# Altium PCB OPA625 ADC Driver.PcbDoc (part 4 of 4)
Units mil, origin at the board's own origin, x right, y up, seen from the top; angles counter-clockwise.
Board outline 4590 x 3930 mil, 4 copper layers (Layer 1 - Top Layer, Layer 2 - GND, Layer 3 - PWR, Layer 4 - Bottom Layer), stack 59.034 mil thick; 428 components, 236 nets, 1203 pads, 546 vias.
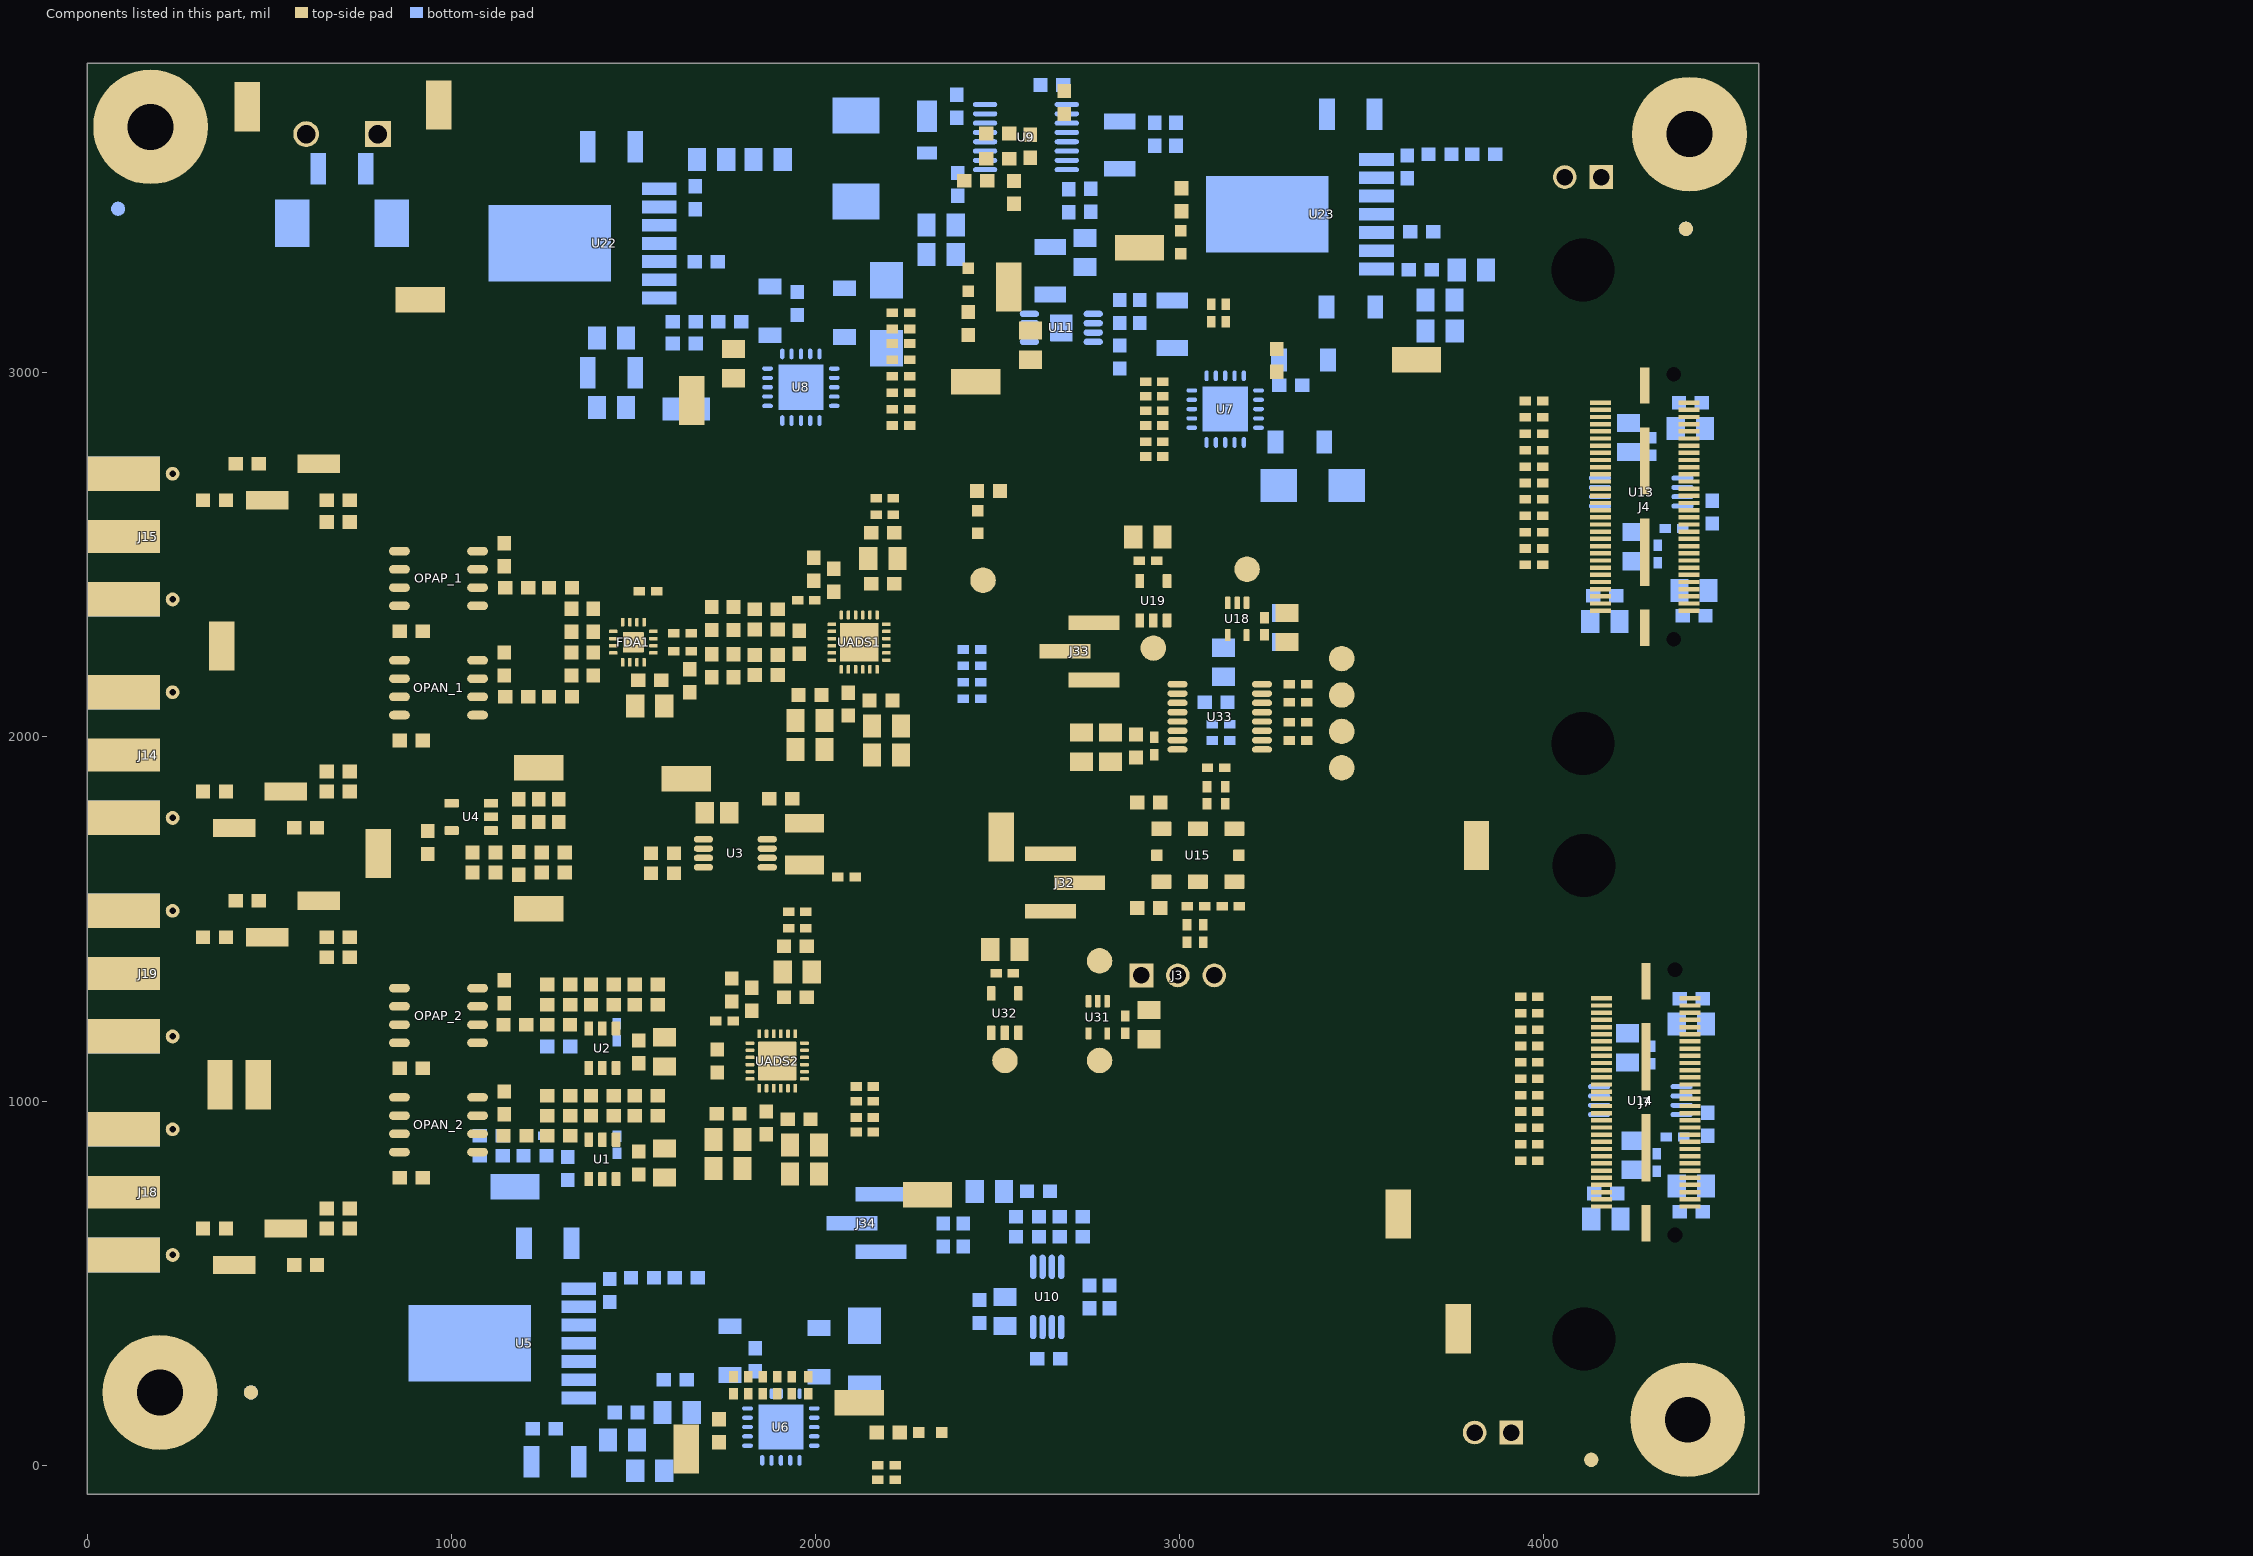
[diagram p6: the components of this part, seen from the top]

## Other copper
Layer 1 - Top Layer:
  region net GND: 4271.85,2222.58 4291.85,2222.58 4291.85,2357.58 4322.34,2388.07 4322.34,2882.08 4291.85,2912.57 4291.85,3042.58 4271.85,3042.58 4261.85,3032.58 4231.85,3002.58 4231.85,2262.58 4261.85,2232.58
  region net GND: 2555.21,3060.7 2630.21,3060.7 2645.21,3075.7 2645.21,3150.7 2655.21,3160.7 2695.21,3160.7 2706.28,3149.63 2706.28,3086.77 2730,3063.05 2745,3048.05 2745,2958.05 2732.65,2945.7 2580.21,2945.7 2555.21,2970.7
  region net GND: 4274.99,1406.32 4294.99,1406.32 4294.99,1271.32 4324.99,1241.32 4324.99,746.32 4294.99,716.32 4294.99,586.32 4274.99,586.32 4264.99,596.32 4235,626.32 4235,1366.32 4264.99,1396.32
  region net GND: 3217.81,2310.8 3332.81,2310.8 3332.81,2430.3 3270,2430.3 3217.81,2378.1
  region net AGND: 2195,2400 2245,2400 2275,2430 2275,2525 2195,2525
  region net 3.3V: 2280,1918 2210,1918 2210,1982 2280,1982
  region net AGND: 2279.45,1998 2279.45,2095 2254.45,2120 2199.45,2120 2190,2120 2190,2080 2210,2060 2210,1998
  region net NetC88_2: 2065,2198 2065,2105 2070,2100 2080,2100 2110,2100 2110,2150 2096,2164 2096,2198
  region net AGND: 1895,2013 1895,2110 1920,2135 1975,2135 1975,2013
  region net NetFDA1_13: 1535,2303 1535,2415 1485,2415 1465,2395 1465,2303
  region net AGND: 1555,2175 1555,2055 1565,2045 1640,2045 1675,2080 1675,2145 1630,2145 1620,2155 1620,2175
  region net 5V: 1535,2217 1535,2055 1525,2045 1455,2045 1455,2160 1465,2170 1465,2217
  region net 3.3V: 2695.01,1960.01 2695.01,1890.01 2705.01,1880.01 2835.01,1880.01 2845.01,1890.01 2845.01,1960.01
  region net GND: 2695.01,1985.01 2695.01,2060.01 2705.01,2070.01 2752.01,2070.01 2762.01,2060.01 2762.01,1985.01
  region net VDD: 3022,1982 2786,1982 2778,1990 2778,2058 2848,2128 3022,2128 3022,2058 2958,2058 2945,2045 2945,2015 2960,2000 3022,2000
  region net AGND: 1955,1265 2005,1265 2035,1295 2035,1390 1955,1390
  region net 3.3V: 2045,765 1985,765 1985,832 2042.45,832 2054.45,820 2054.45,774.45
  region net NetC119_1: 1840,1048 1840,955 1845,950 1855,950 1885,950 1885,1000 1871,1014 1871,1048
  region net 5V: 1670,780 1750,780 1750,847 1670,847
  region net AGND: 1670,863 1670,960 1695,985 1750,985 1750,863
  region net AGND: 1640,840 1495,840 1495,880 1515,900 1630,900 1640,890
  region net 5V: 1440,805 1455,820 1640,820 1640,765 1440,765
  region net AGND: 2048,848 2055,855 2055,925 2010,970 1974.45,970 1965,970 1965,930 1985,910 1985,848
  region net +24VDC: 845,3160 985,3160 985,3286.12 975,3296.12 855,3296.12 845,3286.12
  region net NetC9_1: 1620,2993.54 1620,2853.54 1710,2853.54 1720,2863.54 1720,2983.54 1710,2993.54
  region net +18V: 2305.75,3130 2305.75,2935 2439.46,2935 2511.71,2935 2511.71,3026.49 2445.75,3026.49 2445.75,3130
  region net AGND: 1640,1145 1495,1145 1495,1185 1515,1205 1630,1205 1640,1195
  region net 5V: 1440,1125 1640,1125 1640,1070 1440,1070
  region net AGND: 1270,1660.26 1230,1660.26 1225,1665.26 1225,1705.26 1210,1720.26 1165,1720.26 1150,1735.26 1150,1756.26 1139,1767.26 1089,1767.26 1089,1792.26 1253,1792.26 1260,1785.26 1260,1735.26 1270,1725.26
  region net AGND: 1563.79,1704.41 1569.79,1698.41 1569.79,1605.41 1515.79,1605.41 1504.79,1616.41 1504.79,1645.41 1504.79,1695 1514.2,1704.41
  region net VREF: 1840.79,1677.41 2072.79,1677.41 2079.79,1670.41 2079.79,1605.41 2069.79,1595.41 1875.79,1595.41 1840.79,1630.41
  region net NetC5_2: 2024.79,1735.41 2024.79,1800.41 1974.79,1850.41 1914.79,1850.41 1914.79,1735.41
  region net AGND: 1894.79,1683.41 1894.79,1850.41 1756.79,1850.41 1736.79,1830.41 1736.79,1743.41 1796.79,1683.41
  region net 3.3V: 2907.81,2403.82 2907.81,2602.19 2895,2615 2845,2615 2832.81,2602.81 2832.81,2448.82 2877.81,2403.82
  region net GND: 2919.81,2470.82 2954.81,2470.82 2982.81,2498.82 2982.81,2607.19 2975,2615 2930,2615 2919.81,2604.81
  region net 3.3V: 3174.81,2296.82 3332.81,2296.82 3332.81,2223.82 3317.81,2208.82 3204.81,2208.82 3174.81,2238.82
  region net GND: 2526.83,1338.55 2561.83,1338.55 2589.83,1366.55 2589.83,1466.55 2579.83,1476.55 2540.83,1476.55 2526.83,1462.55
  region net 3.3V: 2513,1271.55 2513,1462 2498.45,1476.55 2451.55,1476.55 2440,1465 2440,1301.38 2469.83,1271.55
  region net GND: 2835.21,1215 2960.21,1215 2970.21,1225 2970.21,1275 2960.21,1285 2870.21,1285 2835.21,1250
  region net 3.3V: 2792.21,1203 2792.21,1168 2820.21,1140 2960.21,1140 2970.21,1150 2970.21,1196 2963.21,1203
  region net -18.5V: 2569.51,3305 2489.51,3305 2474.51,3290 2474.51,3175 2489.51,3160 2569.51,3160
  region net VDDO: 3254,2008 3152,2008 3135,2025 3135,2105 3159,2129 3254,2129 3254,2110 3188,2110 3175,2097 3175,2037 3186,2026 3254,2026
  region net 3.3V: 2048.93,211.07 2048.93,97.07 2078.93,67.07 2188.93,67.07 2188.93,211.07
  region net 5V: 1975,1930 1905,1930 1895,1940 1895,1987 1905,1997 1975,1997
  region net 5V: 1723,1693 1714,1684 1671,1684 1570,1785 1570,1915 1585,1930 1705,1930 1723,1912
  text ".Layer_Name" at 577,-1158.49 h60
Layer 2 - GND:
  text ".Layer_Name" at 577,-1158.49 h60
Layer 3 - PWR:
  region net GND: 760,3545 930,3545 965,3580 965,3660 930,3695 760,3695
  pour cut-out: 4205,1575.49 4205.2,1575.49 cw(c4205.2,1550.25) 4230.44,1550.25 4230.44,1549.95 cw(c4205,1549.95) 4205,1524.51 cw(c4205,1550) 4179.51,1550 cw(c4205,1550)
  pour cut-out: 5770,1830.49 5770.2,1830.49 cw(c5770.2,1805.25) 5795.44,1805.25 5795.44,1804.95 cw(c5770,1804.95) 5770,1779.51 cw(c5770,1805) 5744.51,1805 cw(c5770,1805)
  pour cut-out: 4865,1595.49 4865.2,1595.49 cw(c4865.2,1570.25) 4890.44,1570.25 4890.44,1569.95 cw(c4865,1569.95) 4865,1544.51 cw(c4865,1570) 4839.51,1570 cw(c4865,1570)
  pour cut-out: 4797.95,1575.49 4798.15,1575.49 cw(c4798.15,1550.25) 4823.39,1550.25 4823.39,1549.95 cw(c4797.95,1549.95) 4797.95,1524.51 cw(c4797.95,1550) 4772.46,1550 cw(c4797.95,1550)
  pour cut-out: 5795,2000.49 5795.2,2000.49 cw(c5795.2,1975.25) 5820.44,1975.25 5820.44,1974.95 cw(c5795,1974.95) 5795,1949.51 cw(c5795,1975) 5769.51,1975 cw(c5795,1975)
  pour cut-out: 5770,2264.98 5770.2,2264.98 cw(c5770.2,2239.73) 5795.44,2239.73 5795.44,2239.44 cw(c5770,2239.44) 5770,2214 cw(c5770,2239.49) 5744.51,2239.49 cw(c5770,2239.49)
  pour cut-out: 4187.5,2038.01 4187.7,2038.01 cw(c4187.7,2012.77) 4212.94,2012.77 4212.94,2012.47 cw(c4187.5,2012.47) 4187.5,1987.03 cw(c4187.5,2012.52) 4162.01,2012.52 cw(c4187.5,2012.52)
  pour cut-out: 5785,1965.49 5785.2,1965.49 cw(c5785.2,1940.25) 5810.44,1940.25 5810.44,1939.95 cw(c5785,1939.95) 5785,1914.51 cw(c5785,1940) 5759.51,1940 cw(c5785,1940)
  text ".Layer_Name" at 577,-1158.49 h60
Layer 4 - Bottom Layer:
  region net AGND: 1213.5,1171.5 1283.5,1171.5 1283.5,1121.5 1213.5,1121.5
  region net NetR252_1: 1405,1185 1465,1185 1470,1180 1470,1100 1465,1095 1435,1095 1405,1125
  region net AGND: 1270,805 1340,805 1340,755 1270,755
  region net GND: 3320,2315 3320,2420 3310,2430 3260,2430 3250,2420 3250,2315
  region net GND: 842.76,440 1062.76,660 1232.76,660 1232.76,379 1257.76,354 1376.76,354 1401.76,354 1412.76,365 1578.95,365 1650,425 1650,555 1694,555 1694,105 1625,105 1625,258.61 1578.61,305 1409.56,305 1396.56,318 1257.76,318 1240,300.24 1240,-45 1117.76,-45 842.76,230
  region net -18V: 2851.18,3175.88 3020.18,3175.88 3031.18,3186.88 3031.18,3241.88 2975.05,3298 2851.18,3298
  region net VDDO: 3175,1995 3155,1975 3120,1975 3120,2060 3110,2070 3110,2115 3080,2145 3080,2190 3150,2190 3175,2165
  region net 3.3V: 3080,2215.3 3310,2215.3 3320,2225.3 3320,2290.3 3100.3,2290.3 3080,2270
  region net +24VDC_IN: 685,3680 660,3705 515,3705 380,3570 380,3340 660,3340 685,3365
  region net GND: 740,3515 740,3680 765,3705 935,3705 960,3680 960,3585 860,3585 790,3515
  region net 18.5V: 1630,3218.75 1630,2865 1455,2865 1455,2925.69 1484.31,2955 1484.31,3014.31 1455,3043.61 1455,3139.37 1472.81,3157.19 1472.81,3217.65 1610,3218.61
  region net GND: 1826.02,3200 1944.87,3200 2143.55,3200 2143.54,3350 2000,3350 1944.87,3405.12 1944.87,3613.54 1880,3613.54 1880,3434 1786,3434 1720,3368 1462,3368 1450,3380 1450,3620 1400,3670 1135,3670 1020,3555 1020,3200 1020,3130 1285,2865 1425,2865 1425,3125 1450,3150 1450,3320 1462,3332 1715,3332 1715,3273.62 1730.62,3273.62 1792.12,3212.12 1792.12,3111.46 1826.02,3111.46
  region net GND: 2170,3615 2170,3520 2240,3450 2330,3450 2330,3335 2330,3292.5 2237.5,3292.5 2195,3335 2170,3335 2045,3335 2045,3615
  region net GND: 2643,3240 2600,3240 2600,3191.05 2643,3191.05 2643,3041.05 2600,2998.05 2555,2998.05 2555,2952.05 2850,2952.05 2866,2968.05 2957,2968.05 3030,3041.05 3030,3092.05 2939,3092.05 2888,3041.05 2795,3041.05 2795,3082.05 2785,3092.05 2719,3092.05 2706,3105.05 2706,3240
  region net GND: 3889.76,3490 3889.76,3640 3844.76,3640 3844.76,3530 3774.76,3460 3672.76,3460 3608.76,3460 3598.76,3450 3479.76,3450 3464.76,3465 3464.76,3525 3444.76,3545 3444.76,3820 3369.76,3820 3369.76,3596 3318.76,3545 3064.76,3545 3064.76,3325 3318.76,3325 3369.76,3274 3369.76,3085 3444.76,3085 3444.76,3325 3464.76,3345 3464.76,3399 3479.76,3414 3664.76,3414 3664.76,3360 3789.76,3360 3812.76,3337 3812.76,3250 3889.76,3250 3889.76,3414
  region net -0.2V: 2204.75,787.23 2204.75,677.23 2239.75,642.23 2457.25,642.23 2457.25,689.73 2467.25,699.73 2467.25,787.23
  region net NetC33_1: 2423,419.23 2599,419.23 2609,409.23 2609,358.23 2593,342.23 2457.25,342.23 2423,376.47
  region net 3.3V: 2485.27,435.23 2550.27,435.23 2560.27,445.23 2560.27,507.23 2550.27,517.23 2495.27,517.23 2485.27,507.23
  region net NetR250_1: 1405,860 1418,873 1518,873 1523,868 1523,838 1500,815 1405,815
  text ".Layer_Name" at 577,-1158.49 h60

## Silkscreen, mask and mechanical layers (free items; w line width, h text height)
Top Overlay:
  lines w10: 1615,945 1655,905 1655,635 ; 1640,2520 1640,2505 1760,2505 1760,2520 ; 1665,2325 1665,2505 ; 1635,500 2010,500 2010,635 1635,635 1635,500
  lines w20: 405,3480 455,3480 ; 430,3455 430,3505 ; 935.69,3482.89 985.69,3482.89
  text "-18.5V" at 2468.31,3323.54 h50
  text "-18V" at 2705,3275 h50
  text "+24VDC" at 830,3070 h50
  text "+18V" at 2430,2845 h50
  text "SYSCLK0" at 3495,2155 h50
  text "SYSCLK1" at 3495,2055 h50
  text "SYSCLK2" at 3495,1955 h50
  text "SYSCLK3" at 3495,1855 h50
  text "5V" at 1490,1845 h50
  text "CONVST" at 2435,985 h50
  text "-0.2V" at 2197.25,607.23 h50
  text "3.3V" at 2080,230 h50
  text "TIDA-01050" at 2840,30 h100
  text ".Layer_Name" at 577,-1158.49 h60
Bottom Overlay:
  text "3.3V" at 2260,260 h50 r90
  text ".Layer_Name" at 577,-1158.49 h60
Top Paste:
  text ".Layer_Name" at 577,-1158.49 h60
Bottom Paste:
  text ".Layer_Name" at 577,-1158.49 h60
Top Solder:
  text ".Layer_Name" at 577,-1158.49 h60
  text ".Layer_Name" at 577,-1158.49 h60
Bottom Solder:
  text ".Layer_Name" at 577,-1158.49 h60
Drill Guide:
  text ".Layer_Name" at 577,-1158.49 h60
M1 Board Outline:
  the board outline again, w10
  text ".Layer_Name" at 577,-1158.49 h60
M2 Board Dimensions:
  rectangle: 0,-575 125,-450
  rectangle: 125,-700 500,-575
  lines w7: 0,-575 1000,-575 ; 125,-700 125,-450 ; 250,-700 250,-450 ; 500,-700 500,-450 ; 750,-700 750,-450 ; 0,-700 1000,-700 1000,-450 0,-450 0,-700
  text ".Layer_Name" at 577,-1158.49 h60
M3 3D STEP Top:
  text ".Layer_Name" at 577,-1158.49 h60
M4 3D STEP Bottom:
  text ".Layer_Name" at 577,-1158.49 h60
M5 Assembly Top:
  lines w10: -292,-1230.17 6308,-1230.17 ; -292,-1026.83 6310,-1026.83 ; -292,-823.5 -292,-1433.5 3713,-1433.5 6310,-1433.5 6310,-823.5 -291.5,-823.5 -291.5,-1433.5 1284,-1433.5 ; 2173,-1433.5 2173,-823.5 ; 3440,-1026.83 3440,-823.5 ; 4280,-1026.83 4280,-823.5 ; 4902,-1440 4902,-1237.17
  text "COMPONENTS MARKED 'DNP' SHOULD NOT BE POPULATED." at 1153.5,-618.5 h60
  text "ASSEMBLY VARIANT:" at 1153,-734 h60
  text ".VariantName" at 2189,-734 h60
  text "PCB VIEWED FROM TOP SIDE" at -228.5,-955.67 h60
  text "BOARD #:" at 2248,-955.67 h60
  text ".PRJ_Number" at 2793.5,-955.67 h60
  text "REV:" at 3638,-955.67 h60
  text ".PCB_Rev" at 3929.5,-955.67 h60
  text "SVN REV:" at 4476,-955.67 h60
  text ".VersionControl_RevNumber" at 4982,-955.67 h60
  text "TID #:" at 2248,-1159 h60
  text ".TID" at 2793.5,-1159 h60
  text "PLOT NAME =" at -228.5,-1364.34 h60
  text ".plot_File_Name" at 577,-1364.34 h60
  text "GENERATED    :" at 2250,-1364.34 h60
  text ".Print_Date" at 3119.5,-1364.34 h60
  text ".Print_Time" at 3848.5,-1364.34 h60
  text "TEXAS INSTRUMENTS" at 5113,-1364.34 h60
M6 Assembly Bottom:
  lines w10: -292.5,-1027.33 6309.5,-1027.33 ; -290.5,-1230.67 6309.5,-1230.67 ; 1115.5,-1440.5 1115.5,-1237.67 ; 1737.5,-1027.33 1737.5,-824 ; 2577.5,-1027.33 2577.5,-824 ; 3844.5,-1434 3844.5,-824 ; 4733.5,-1434 6309,-1434 6309,-824 -292.5,-824 -292.5,-1434 2304.5,-1434 6309.5,-1434 6309.5,-824
  text "COMPONENTS MARKED 'DNP' SHOULD NOT BE POPULATED." at 6102,-618 h60
  text ".VariantName" at 5058,-734 h60
  text "ASSEMBLY VARIANT:" at 6097,-734 h60
  text ".VersionControl_RevNumber" at 1035.5,-956.17 h60
  text "SVN REV:" at 1541.5,-956.17 h60
  text ".PCB_Rev" at 2088,-956.17 h60
  text "REV:" at 2379.5,-956.17 h60
  text ".PRJ_Number" at 3224,-956.17 h60
  text "BOARD #:" at 3769.5,-956.17 h60
  text "PCB VIEWED FROM BOTTOM SIDE" at 6246,-956.17 h60
  text ".TID" at 3224,-1159.5 h60
  text "TID #:" at 3769.5,-1159.5 h60
  text "TEXAS INSTRUMENTS" at 904.5,-1364.84 h60
  text ".Print_Time" at 2169,-1364.84 h60
  text ".Print_Date" at 2898,-1364.84 h60
  text "GENERATED    :" at 3767.5,-1364.84 h60
  text ".plot_File_Name" at 5440.5,-1364.84 h60
  text "PLOT NAME =" at 6246,-1364.84 h60
M9 Title Sheet:
  drawing of 1178 lines, arcs and shapes, not listed
  text "1" at 739.84,7736.5 h70
  text "2" at 3235.5,7736.5 h70
  text "3" at 5724.84,7736.5 h70
  text "4" at 8231.51,7736.5 h70
  text "5" at 10730.5,7736.5 h70
  text "6" at 13235.5,7736.5 h70
  text "A" at -416.5,6593.5 h70
  text "A" at 14383.5,6593.5 h70
  text "B" at -416.5,4213.5 h70
  text "B" at 14383.5,4213.5 h70
  text "C" at -416.5,1838.5 h70
  text "C" at 14383.5,1838.5 h70
  text "PROJECT TITLE:" at 11343.5,-22.5 h45
  text ".PRJ_Title" at 11393.5,-155.83 h70
  text "DESIGNED FOR:" at 11343.5,-323.5 h45
  text ".PRJ_Customer" at 11393.5,-463.5 h70
  text "D" at -416.5,-531.5 h70
  text "D" at 14383.5,-531.5 h70
  text "FILE NAME:" at 11343.5,-623.5 h45
  text ".PCB_File_Name_No_Path" at 11393.5,-743.5 h70
  text "Texas Instruments (TI) and/or its licensors do not warrant the accuracy or completeness of this specification" at 6374,-905.34 h45
  text "ENGINEER:" at 11343.5,-913.5 h45
  text "LAYOUT BY:" at 12848.5,-913.5 h45
  text "or any information contained therein. TI and/or its licensors do not warrant that this design will meet" at 6329.01,-1018 h45
  text ".PRJ_Engineer" at 11393.5,-1068.49 h70
  text "s  o  l  u  t  i  o  n  s" at 13709,-1105 h68
  text "the specifications, will be suitable for your application or fit for any particular purpose, or will operate in" at 6329.01,-1130.67 h45
  text ".Layer_Name" at 577,-1158.49 h60
  text "ALTIUM DESIGNER VERSION:" at 12848.5,-1223.5 h45
  text "an implementation. TI and/or its licensors do not warrant that the design is production worthy. You should" at 6329.01,-1243.33 h45
  text "completely validate and test your design implementation to confirm the system functionality for your application." at 6374,-1356 h45
  text ".print_Scale" at 11393.5,-1356.83 h70
  text ".Application_BuildNumber" at 12899,-1356.83 h70
  text "1" at 739.84,-1563.5 h70
  text "2" at 3235.5,-1563.5 h70
  text "3" at 5724.84,-1563.5 h70
  text "4" at 8231.51,-1563.5 h70
  text "5" at 10730.5,-1563.5 h70
  text "6" at 13235.5,-1563.5 h70
M10 Fab Notes:
  drawing of 173 lines, arcs and shapes, not listed
  text "DESIGN INFORMATION" at 12377.02,5901 h60
  text "MIN. TRACK WIDTH:" at 11732.46,5721 h60
  text "8" at 12828.7,5721 h60
  text "MIL" at 12983.46,5721 h60
  text "MIN. CLEARANCE:" at 11732.46,5589 h60
  text "0.2" at 12768.7,5589 h60
  text "mm" at 12983.46,5589 h60
  text "MIN. VIA PAD SIZE:" at 11732.46,5457 h60
  text "20" at 12798.71,5457 h60
  text "MIL" at 12983.46,5457 h60
  text "0.05mm (2MIL)" at 12427.46,5315.29 h60
  text "MINIMUM ANNULAR RING" at 11403.23,5311 h60
  text "EXTERNAL" at 13135.46,5311 h60
  text "PER" at 11603.23,5193 h60
  text "IPC-D-275 CLASS 2 LEVEL C" at 11823.23,5193 h60
  text "MIL, HOLES" at 13311.46,5080.71 h60
  text "+/-" at 12919,5080 h60
  text "+/-" at 13773,5080 h60
  text "REGISTRATION TOLERANCES:" at 11403.23,5075 h60
  text "METAL" at 12603,5075 h60
  text "5" at 13179.2,5075 h60
  text "3" at 14012.2,5075 h60
  text "MIL" at 14128.46,5075 h60
  text "+/-" at 13773,4962 h60
  text "HOLE SIZE TOLERANCE (UNLESS OTHERWISE SPECIFIED):" at 11403.23,4957 h60
  text "3" at 14012.2,4957 h60
  text "MIL" at 14128.46,4957 h60
  text "MATERIAL:" at 11328.46,4747.54 h60
  text "FR-4 High Tg" at 12314.9,4607.21 h60
  text "FR-408" at 11749.46,4598.64 h60
  text "OTHER" at 13237.46,4598.64 h60
  text "X" at 12160,4595 h60
  text "62 MIL (1.6mm) +/-10%" at 12069.56,4435.92 h60
  text "THICKNESS:" at 11403.23,4431.64 h60
  text "X" at 11941.4,4431.64 h60
  text "OTHER" at 13354.46,4431.64 h60
  text "TOLERANCE:" at 11403.23,4273.64 h60
  text "X" at 12242.53,4273.64 h60
  text "ANSI IPC-6012 TYPE 3 CLASS 2" at 12429.48,4273.64 h60
  text "OTHER +/-" at 12429.46,4117.64 h60
  text "BOW & TWIST:" at 11403.23,3960.64 h60
  text "X" at 12242.53,3960.64 h60
  text "ANSI IPC-6012 TYPE 3 CLASS 2" at 12429.48,3960.64 h60
  text "OTHER +/-" at 12429.46,3802.13 h60
  text "DRILLING:" at 11328.46,3663.64 h60
  text "REFERENCE:" at 11403.23,3546.64 h60
  text "X" at 12051.46,3546.64 h60
  text "AS SHOWN" at 12238.46,3546.64 h60
  text "X" at 12952.46,3546.64 h60
  text "NC_DRILL FILES" at 13089.46,3546.64 h60
  text "PTH COPPER THICKNESS:" at 11403.23,3388.64 h60
  text "X" at 12533.46,3388.64 h60
  text "20-30 um" at 12670.46,3388.64 h60
  text "OTHER" at 13387.46,3388.64 h60
  text "BOARD FINISH:" at 11328.46,3229.64 h60
  text "SILKSCREEN:" at 11483.68,3111.64 h60
  text "X" at 12432.46,3111.64 h60
  text "TOP" at 12558.46,3111.64 h60
  text "X" at 12942.46,3111.64 h60
  text "BOTTOM" at 13069.46,3111.64 h60
  text "SILKSCREEN COLOR:" at 11483.68,2944.64 h60
  text "X" at 12431.42,2944.64 h60
  text "WHITE" at 12558.46,2944.64 h60
  text "OTHER" at 13069.46,2944.64 h60
  text "X" at 12562.42,2785.44 h60
  text "GREEN" at 12689.46,2785.44 h60
  text "OTHER" at 13307.46,2785.44 h60
  text "SOLDER RESIST COLOR:" at 11483.68,2774.64 h60
  text "X" at 12562.42,2615.44 h60
  text "MATTE" at 12689.46,2615.44 h60
  text "SEMI-GLOSS" at 13307,2614.8 h60
  text "IMMERSION GOLD (ENIG)" at 12389.46,2426.92 h60
  text "ENEPIG" at 13727,2423.64 h60
  text "SURFACE FINISH:" at 11328.46,2422.64 h60
  text "X" at 12202.51,2422.64 h60
  text "IMM. TIN/SILVER OR EQUIV" at 11658,2265.64 h60
  text "OTHER" at 13089.46,2265.64 h60
  text "ARRAY/PANEL:" at 11328.46,2086.64 h60
  text "CUT AND TRIM PER M1 BOARD OUTLINE" at 12389.46,2082.35 h60
  text "N.C. ROUTE" at 12389.46,1930.64 h60
  text "X" at 13068.46,1930.64 h60
  text "V. SCORE" at 13255.46,1930.64 h60
  text "CERTIFICATION:" at 11328.46,1793.64 h60
  text "MATERIALS AND WORKMANSHIP FOR ALL PCBS" at 12053.46,1793.64 h60
  text "TO MEET OR EXCEED THE REQUIREMENTS OF:" at 12053.46,1695.64 h60
  text "X" at 11679.96,1559.13 h60
  text "ANSI IPC-A-600F CLASS ->" at 11818.96,1559.13 h60
  text "X" at 13458.02,1559.13 h60
  text "2" at 13576.96,1559.14 h60
  text "1" at 13261.96,1557.64 h60
  text "3" at 13930.96,1557.64 h60
  text "X" at 12494.02,1399.64 h60
  text "RoHS" at 12630.96,1399.64 h60
  text "OTHER" at 13275.36,1399.64 h60
  text "PER ORDER" at 13672.42,1399.64 h60
  text "ALL BOARDS MUST MEET OR EXCEED UL94-V0 REQUIREMENTS." at 11356,1234 h60
  text "PCB MUST BEAR THE UL94V-0 UL REGISTERED MATERIAL ID NUMBER" at 11356,1114 h60
  text "ADDITIONAL REQUIREMENTS:" at 11328.46,940.64 h60
  text "MICROSECTION:" at 11403.23,825.64 h60
  text "YES" at 12308.96,825.64 h60
  text "REQUIRED" at 13170.46,669.49 h60
  text "BARE BOARD ELEC. TEST:" at 11403.23,666.64 h60
  text "NONE" at 12708.96,666.64 h60
  text "X" at 13043.46,666.64 h60
  text "PER ORDER" at 13762.46,666.64 h60
  text ".Layer_Name" at 577,-1158.49 h60
M11 Gerber Information:
  lines w10: -292,-1230.17 6308,-1230.17 ; -292,-1026.83 6310,-1026.83 ; -292,-823.5 -292,-1433.5 3713,-1433.5 6310,-1433.5 6310,-823.5 -291.5,-823.5 -291.5,-1433.5 1284,-1433.5 ; 2173,-1433.5 2173,-823.5 ; 3440,-1026.83 3440,-823.5 ; 4280,-1026.83 4280,-823.5 ; 4902,-1440 4902,-1237.17
  text "ALL ARTWORK VIEWED FROM TOP SIDE" at -228.5,-955.67 h60
  text "BOARD #:" at 2248,-955.67 h60
  text ".PRJ_Number" at 2793.5,-955.67 h60
  text "REV:" at 3638,-955.67 h60
  text ".PCB_Rev" at 3929.5,-955.67 h60
  text "SVN REV:" at 4476,-955.67 h60
  text ".VersionControl_RevNumber" at 4982,-955.67 h60
  text "LAYER NAME =" at -228.5,-1158.49 h60
  text "TID #:" at 2248,-1159 h60
  text ".TID" at 2793.5,-1159 h60
  text "PLOT NAME =" at -228.5,-1364.34 h60
  text ".plot_File_Name" at 577,-1364.34 h60
  text "GENERATED    :" at 2250,-1364.34 h60
  text ".Print_Date" at 3119.5,-1364.34 h60
  text ".Print_Time" at 3848.5,-1364.34 h60
  text "TEXAS INSTRUMENTS" at 5113,-1364.34 h60
M12 Stackup:
  drawing of 295 lines, arcs and shapes, not listed
  text "Layer" at 9307.5,7532.5 h60
  text "Name" at 9717.41,7532.5 h60
  text "Material" at 11127,7532.5 h60
  text "Thickness" at 11986.77,7532.5 h60
  text "Constant" at 12636.6,7532.5 h60
  text "Board Layer Stack" at 13206.47,7532.5 h60
  text "1" at 9307.5,7412.5 h60
  text "Top Overlay" at 9717.41,7412.5 h60
  text "2" at 9307.5,7292.5 h60
  text "Top Solder" at 9717.41,7292.5 h60
  text "Solder Resist" at 11127,7292.5 h60
  text "0.40mil" at 11986.77,7292.5 h60
  text "3.5" at 12636.6,7292.5 h60
  text "3" at 9307.5,7172.5 h60
  text "Layer 1 - Top Layer" at 9717.41,7172.5 h60
  text "Copper" at 11127,7172.5 h60
  text "1.40mil" at 11986.77,7172.5 h60
  text "4" at 9307.5,7052.5 h60
  text "Dielectric 1" at 9717.41,7052.5 h60
  text "370HR" at 11127,7052.5 h60
  text "5.20mil" at 11986.77,7052.5 h60
  text "4.2" at 12636.6,7052.5 h60
  text "5" at 9307.5,6932.5 h60
  text "Layer 2 - GND" at 9717.41,6932.5 h60
  text "Copper" at 11127,6932.5 h60
  text "1.42mil" at 11986.77,6932.5 h60
  text "6" at 9307.5,6812.5 h60
  text "Dielectric 2" at 9717.41,6812.5 h60
  text "370HR" at 11127,6812.5 h60
  text "43.00mil" at 11986.77,6812.5 h60
  text "4.2" at 12636.6,6812.5 h60
  text "7" at 9307.5,6692.5 h60
  text "Layer 3 - PWR" at 9717.41,6692.5 h60
  text "Copper" at 11127,6692.5 h60
  text "1.42mil" at 11986.77,6692.5 h60
  text "8" at 9307.5,6572.5 h60
  text "Dielectric 3" at 9717.41,6572.5 h60
  text "370HR" at 11127,6572.5 h60
  text "5.20mil" at 11986.77,6572.5 h60
  text "4.2" at 12636.6,6572.5 h60
  text "9" at 9307.5,6452.5 h60
  text "Layer 4 - Bottom Layer" at 9717.41,6452.5 h60
  text "Copper" at 11127,6452.5 h60
  text "1.40mil" at 11986.77,6452.5 h60
  text "10" at 9307.5,6332.5 h60
  text "Bottom Solder" at 9717.41,6332.5 h60
  text "Solder Resist" at 11127,6332.5 h60
  text "0.40mil" at 11986.77,6332.5 h60
  text "3.5" at 12636.6,6332.5 h60
  text "11" at 9307.5,6212.5 h60
  text "Bottom Overlay" at 9717.41,6212.5 h60
  text ".Layer_Name" at 577,-1158.49 h60
M13 Component Bodies Top:
  text ".Layer_Name" at 577,-1158.49 h60
M14 Component Bodies Bottom:
  text ".Layer_Name" at 577,-1158.49 h60
M15 Courtyards Top:
  text ".Layer_Name" at 577,-1158.49 h60
M16 Courtyards Bottom:
  text ".Layer_Name" at 577,-1158.49 h60
Drill Drawing:
  circle w10: c7008.9,555.42 r22.14
  lines w10: 6986.76,632.91 7031.04,632.91 7031.04,677.18 6986.76,677.18 6986.76,632.91 ; 6986.76,732.53 6986.76,743.6 6997.83,754.67 6986.76,765.74 6986.76,776.81 6997.83,776.81 7008.9,765.74 7019.97,776.81 7031.04,776.81 7031.04,765.74 7019.97,754.67 7031.04,743.6 7031.04,732.53 7019.97,732.53 7008.9,743.6 6997.83,732.53 6986.76,732.53 ; 6986.76,876.43 7031.04,876.43 7008.9,832.15 6986.76,876.43 ; 6986.76,931.77 7031.04,931.77 7031.04,976.05 6986.76,976.05 6986.76,931.77 ; 6986.76,1042.47 6997.83,1042.47 6997.83,1031.4 7019.97,1031.4 7019.97,1042.47 7031.04,1042.47 7031.04,1064.6 7019.97,1064.6 7019.97,1075.67 6997.83,1075.67 6997.83,1064.6 6986.76,1064.6 6986.76,1042.47 ; 6986.76,1153.16 7008.9,1131.02 7031.04,1153.16 7008.9,1175.3 6986.76,1153.16 ; 6986.76,1230.64 7008.9,1241.71 7031.04,1230.64 7019.97,1252.78 7031.04,1274.92 7008.9,1263.85 6986.76,1274.92 6997.83,1252.78 6986.76,1230.64 ; 6995.62,940.63 7022.18,940.63 7022.18,967.2 6995.62,967.2 6995.62,940.63
  lines w12: 6946,503.4 10527.58,503.4 ; 6946,1300.38 10527.58,1300.38 ; 7261.63,403.78 7261.63,1400 ; 7578.82,403.78 7578.82,1400 ; 8200.56,403.78 8200.56,1400 ; 8444.88,403.78 8444.88,1400 ; 8805.22,403.78 8805.22,1400 ; 9983.38,403.78 9983.38,1400 ; 6946,403.78 10527.58,403.78 10527.58,1400 6946,1400 6946,403.78
  text "Symbol" at 7005.77,1330.26 h72
  text "Quantity" at 7291.52,1330.26 h72
  text "Finished Hole Size" at 7608.7,1330.26 h72
  text "Plated" at 8230.45,1330.26 h72
  text "Hole Type" at 8474.77,1330.26 h72
  text "Drill Layer Pair" at 8835.11,1330.26 h72
  text "Hole Tolerance" at 10013.26,1330.26 h72
  text "4" at 7291.52,1230.64 h60
  text "40.00mil (1.016mm)" at 7608.7,1230.64 h60
  text "NPTH" at 8230.45,1230.64 h60
  text "Round" at 8474.77,1230.64 h60
  text "Layer 1 - Top Layer - Layer 4 - Bottom Layer" at 8835.11,1230.64 h60
  text "4" at 7291.52,1131.02 h60
  text "173.23mil (4.400mm)" at 7608.7,1131.02 h60
  text "NPTH" at 8230.45,1131.02 h60
  text "Round" at 8474.77,1131.02 h60
  text "Layer 1 - Top Layer - Layer 4 - Bottom Layer" at 8835.11,1131.02 h60
  text "34" at 7291.52,1031.4 h60
  text "7.87mil (0.200mm)" at 7608.7,1031.4 h60
  text "PTH" at 8230.45,1031.4 h60
  text "Round" at 8474.77,1031.4 h60
  text "Layer 1 - Top Layer - Layer 4 - Bottom Layer" at 8835.11,1031.4 h60
  text "512" at 7291.52,931.77 h60
  text "10.00mil (0.254mm)" at 7608.7,931.77 h60
  text "PTH" at 8230.45,931.77 h60
  text "Round" at 8474.77,931.77 h60
  text "Layer 1 - Top Layer - Layer 4 - Bottom Layer" at 8835.11,931.77 h60
  text "8" at 7291.52,832.15 h60
  text "18.00mil (0.457mm)" at 7608.7,832.15 h60
  text "PTH" at 8230.45,832.15 h60
  text "Round" at 8474.77,832.15 h60
  text "Layer 1 - Top Layer - Layer 4 - Bottom Layer" at 8835.11,832.15 h60
  text "7" at 7291.52,732.53 h60
  text "45.28mil (1.150mm)" at 7608.7,732.53 h60
  text "PTH" at 8230.45,732.53 h60
  text "Round" at 8474.77,732.53 h60
  text "Layer 1 - Top Layer - Layer 4 - Bottom Layer" at 8835.11,732.53 h60
  text "2" at 7291.52,632.91 h60
  text "51.18mil (1.300mm)" at 7608.7,632.91 h60
  text "PTH" at 8230.45,632.91 h60
  text "Round" at 8474.77,632.91 h60
  text "Layer 1 - Top Layer - Layer 4 - Bottom Layer" at 8835.11,632.91 h60
  text "4" at 7291.52,533.29 h60
  text "125.98mil (3.200mm)" at 7608.7,533.29 h60
  text "PTH" at 8230.45,533.29 h60
  text "Round" at 8474.77,533.29 h60
  text "Layer 1 - Top Layer - Layer 4 - Bottom Layer" at 8835.11,533.29 h60
  text "575 Total" at 7291.52,433.66 h60
  text ".Layer_Name" at 577,-1158.49 h60

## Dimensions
0,-700 to 1000,-700 on M2 Board Dimensions
0,-80 to 4590,-80 on M2 Board Dimensions
0,-80 to 0,3850 on M2 Board Dimensions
